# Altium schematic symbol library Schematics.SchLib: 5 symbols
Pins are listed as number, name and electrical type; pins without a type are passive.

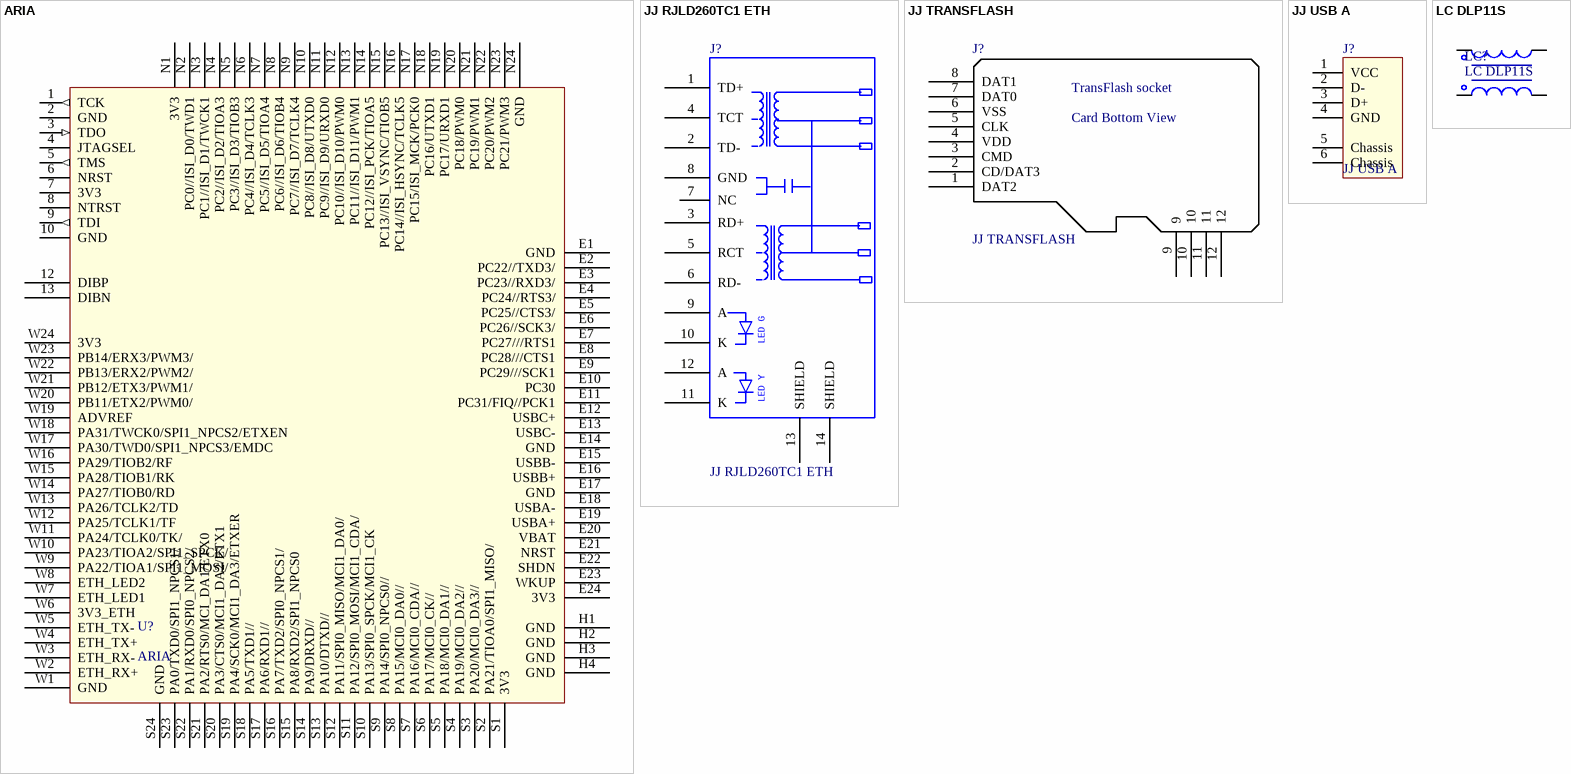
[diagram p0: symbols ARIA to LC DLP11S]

## ARIA
designator U?
footprint AB ARIA 1
footprint AB ARIA 3
pins: 1 TCK (out), 2 GND (power), 3 TDO (in), 4 JTAGSEL, 5 TMS (out), 6 NRST, 7 3V3 (power), 8 NTRST, 9 TDI (out), 10 GND, 12 DIBP, 13 DIBN, E1 GND, E2 PC22//TXD3/, E3 PC23//RXD3/, E4 PC24//RTS3/, E5 PC25//CTS3/, E6 PC26//SCK3/, E7 PC27///RTS1, E8 PC28///CTS1, E9 PC29///SCK1, E10 PC30, E11 PC31/FIQ//PCK1, E12 USBC+, E13 USBC-, E14 GND, E15 USBB-, E16 USBB+, E17 GND, E18 USBA-, E19 USBA+, E20 VBAT, E21 NRST, E22 SHDN, E23 WKUP, E24 3V3, H1 GND, H2 GND, H3 GND, H4 GND, N1 3V3, N2 PC0//ISI_D0/TWD1, N3 PC1//ISI_D1/TWCK1, N4 PC2//ISI_D2/TIOA3, N5 PC3//ISI_D3/TIOB3, N6 PC4//ISI_D4/TCLK3, N7 PC5//ISI_D5/TIOA4, N8 PC6//ISI_D6/TIOB4, N9 PC7//ISI_D7/TCLK4, N10 PC8//ISI_D8/UTXD0, N11 PC9//ISI_D9/URXD0, N12 PC10//ISI_D10/PWM0, N13 PC11//ISI_D11/PWM1, N14 PC12//ISI_PCK/TIOA5, N15 PC13//ISI_VSYNC/TIOB5, N16 PC14//ISI_HSYNC/TCLK5, N17 PC15/ISI_MCK/PCK0, N18 PC16/UTXD1, N19 PC17/URXD1, N20 PC18/PWM0, N21 PC19/PWM1, N22 PC20/PWM2, N23 PC21/PWM3, N24 GND, S1 3V3, S2 PA21/TIOA0/SPI1_MISO/, S3 PA20/MCI0_DA3//, S4 PA19/MCI0_DA2//, S5 PA18/MCI0_DA1//, S6 PA17/MCI0_CK//, S7 PA16/MCI0_CDA//, S8 PA15/MCI0_DA0//, S9 PA14/SPI0_NPCS0//, S10 PA13/SPI0_SPCK/MCI1_CK, S11 PA12/SPI0_MOSI/MCI1_CDA/, S12 PA11/SPI0_MISO/MCI1_DA0/, S13 PA10/DTXD//, S14 PA9/DRXD//, S15 PA8/RXD2/SPI1_NPCS0, S16 PA7/TXD2/SPI0_NPCS1/, S17 PA6/RXD1//, S18 PA5/TXD1//, S19 PA4/SCK0/MCI1_DA3/ETXER, S20 PA3/CTS0/MCI1_DA2/ETX1, S21 PA2/RTS0/MCI_DA1/ETX0, S22 PA1/RXD0/SPI0_NPCS2/, S23 PA0/TXD0/SPI1_NPCS1/, S24 GND, W1 GND (power), W2 ETH_RX+, W3 ETH_RX-, W4 ETH_TX+, W5 ETH_TX-, W6 3V3_ETH, W7 ETH_LED1, W8 ETH_LED2, W9 PA22/TIOA1/SPI1_MOSI/, W10 PA23/TIOA2/SPI1_SPCK/, W11 PA24/TCLK0/TK/, W12 PA25/TCLK1/TF, W13 PA26/TCLK2/TD, W14 PA27/TIOB0/RD, W15 PA28/TIOB1/RK, W16 PA29/TIOB2/RF, W17 PA30/TWD0/SPI1_NPCS3/EMDC, W18 PA31/TWCK0/SPI1_NPCS2/ETXEN, W19 ADVREF, W20 PB11/ETX2/PWM0/, W21 PB12/ETX3/PWM1/, W22 PB13/ERX2/PWM2/, W23 PB14/ERX3/PWM3/, W24 3V3

## JJ RJLD260TC1 ETH
designator J?
ETH connector RJLD-260TC1 TAIMAG; Right: 100; Bottom: 240
footprint RJLD-260TC1 (RJ45 Ethernet connector by TAIMAG)
pins: 1 TD+, 2 TD-, 3 RD+, 4 TCT, 5 RCT, 6 RD-, 7 NC, 8 GND, 9 A, 10 K, 11 K, 12 A, 13 SHIELD, 14 SHIELD

## JJ TRANSFLASH
designator J?
Transflash Socket
footprint microSD Socket
pins: 1 DAT2, 2 CD/DAT3, 3 CMD, 4 VDD, 5 CLK, 6 VSS, 7 DAT0, 8 DAT1, 9, 10, 11, 12

## JJ USB A
designator J?
USB 2.0 type A; Right: 30; Bottom: 70
footprint USB2.0-4H4 3D FOX (Connector; USB1.1, Type A, Thru-Hole; 4 Position; Right Angle)
pins: 1 VCC, 2 D-, 3 D+, 4 GND, 5 Chassis, 6 Chassis

## LC DLP11S
designator LC?
Common Mode Choke Coil Film Type; Right: 10; Bottom: 40
footprint LC 0504 (1210 metric)
footprint LC 2020 (5050 metric)
pins: 1, 2, 3, 4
